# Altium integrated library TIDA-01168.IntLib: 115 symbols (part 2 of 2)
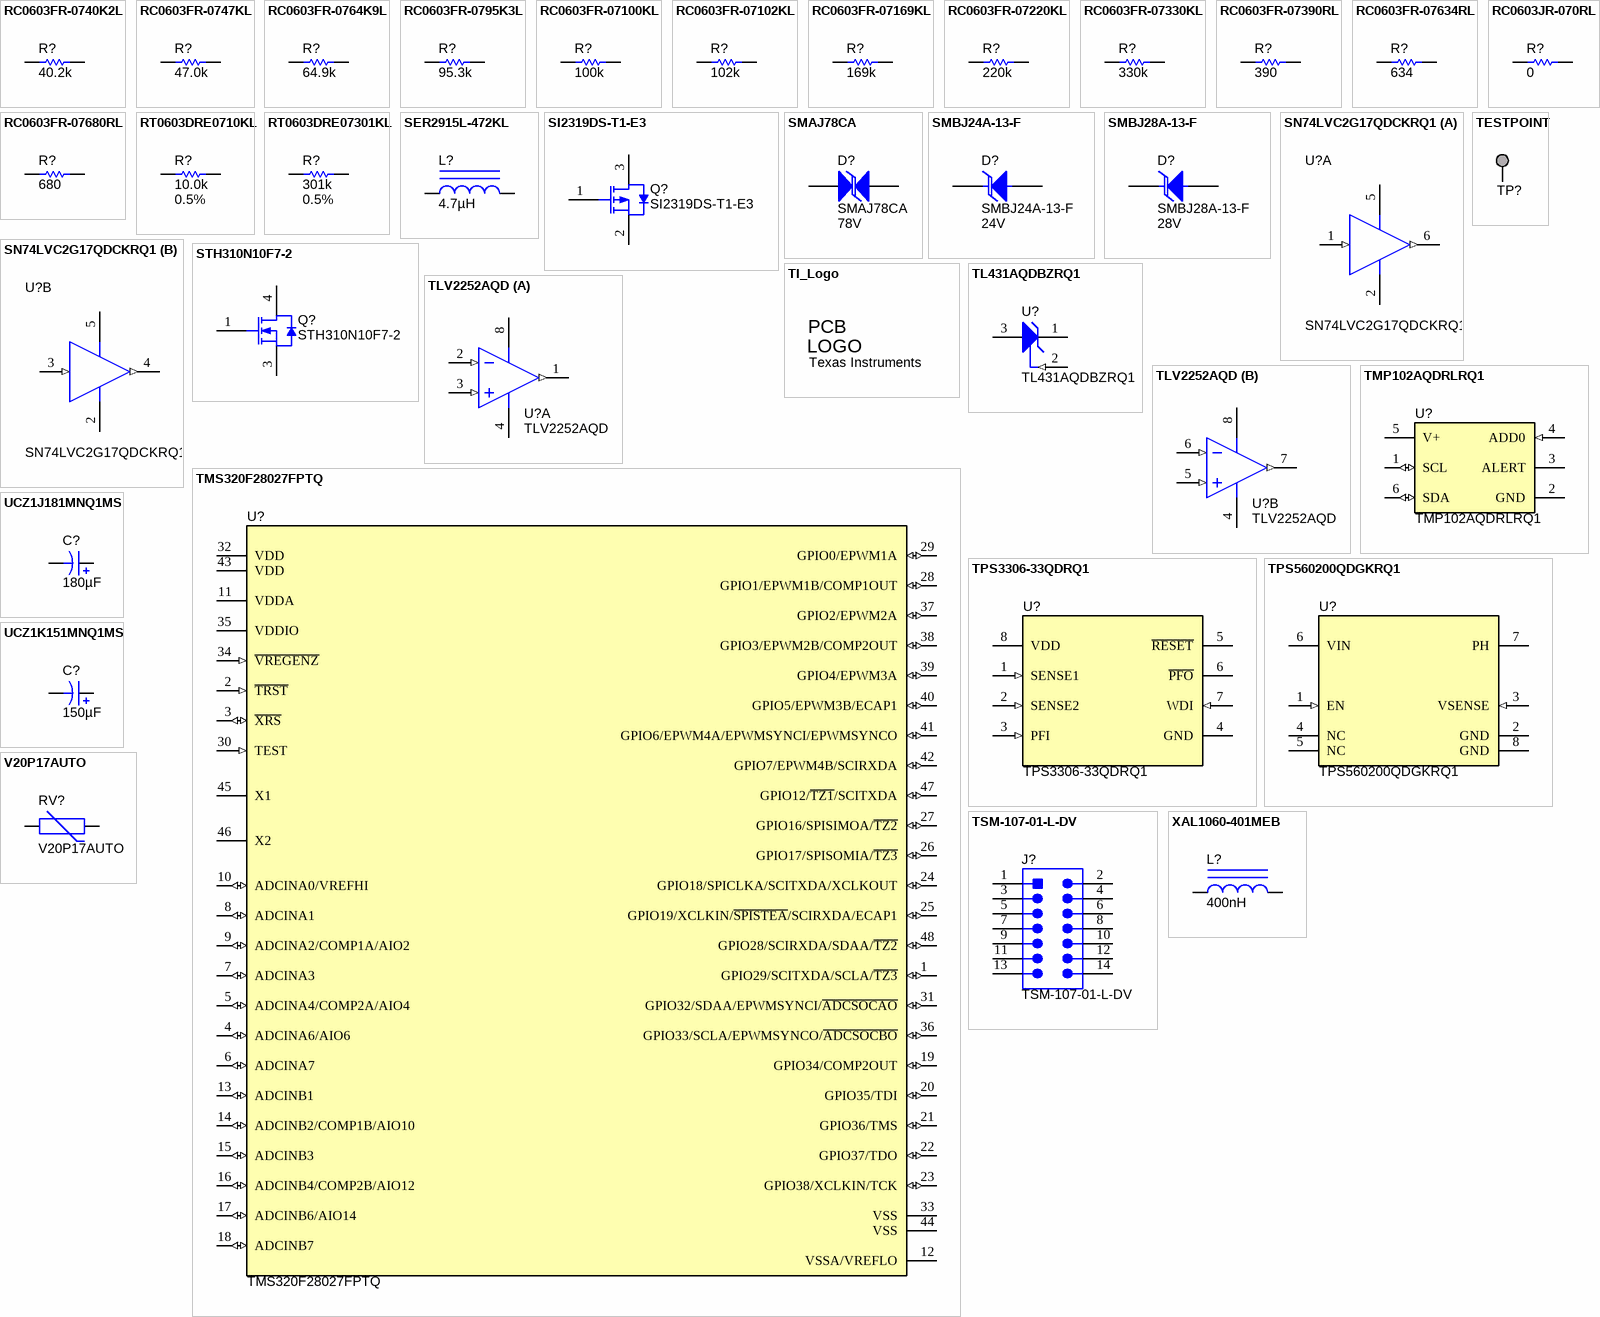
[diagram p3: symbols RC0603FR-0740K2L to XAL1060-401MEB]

## TESTPOINT
designator TP?  (value not drawn)  (no BOM)
TEST POINT.  No entry in BOM.
footprint TESTPOINT
footprint TP_VIA_018RND008
footprint TP_VIA_060RND040
footprint TP_25MIL-SMT
footprint TP_50MIL-25MILHOLE
footprint TP_60MIL-SMT
pins: 1

## TI_Logo
designator Logo?, comment Texas Instruments  (no BOM)
Texas Instrument Corporate Signature; SymbolCreator: codlsc
footprint TI_Stacked_SolderMask_Medium
footprint TI_Stacked_SolderMask_Small
footprint TI_Stacked_Overlay_Medium
footprint TI_Stacked_Overlay_Small
footprint TI_Horizontal_SolderMask_Medium
footprint TI_Horizontal_SolderMask_Small
footprint TI_Horizontal_Overlay_Medium
footprint TI_Horizontal_Overlay_Small
footprint TI_Symbol_SolderMask_Small
footprint TI_Symbol_Overlay_Medium
footprint TI_Symbol_Overlay_Small
footprint TI_Symbol_SolderMask_Medium

## TL431AQDBZRQ1
designator U?
Automotive Catalog Adjustable Precision Shunt Regulator, 34 ppm / degC, 100 mA, -40 to 125 degC, 3-pin SOT-23 (DBZ), Green (RoHS & no Sb/Br); Manufacturer: Texas Instruments; Alternate PartNumber: Equivalent; Initial Accuracy @ 25/deg C(%): 1; Iout/Iz(Max)(mA): 100; Min Iz for Regulation(uA): 600; SubFamily: Shunt Voltage Reference; Temp Coeff(Typ)(ppm/ degree C): 34; VO Adj(Max)(V): 36; VO Adj(Min)(V): 2.495
footprint DBZ0003A_N (SOT23, 3-Leads, Body 2.92x1.3 mm, Pitch 0.95 mm, IPC Medium Density)
footprint DBZ0003A_L (SOT23, 3-Leads, Body 2.92x1.3 mm, Pitch 0.95 mm, IPC High Density)
footprint DBZ0003A_M (SOT23, 3-Leads, Body 2.92x1.3 mm, Pitch 0.95 mm, IPC Low Density)
pins: 1 CATHODE, 2 REF (in), 3 ANODE (power)

## TLV2252AQD
designator U?
Low-Voltage Rail-to-Rail Dual Operational Amplifier, 2.7 to 8 V, -40 to 125 degC, 8-pin SOIC (D0008A), Green (RoHS & no Sb/Br); Manufacturer: Texas Instruments; Alternate PartNumber: Equivalent; CMRR(Min)(dB): 65; IIB(Max)(pA): 60; Iq per channel(Max)(mA): 0.0625; Number of Channels: 2; Offset Drift(Typ)(uV/C): 0.5; Slew Rate(Typ)(V/us): 0.1; Sub Family: Low Power Amp (<=500uA), Low Supply Voltage Amplifier (<=2.7V), Precision Amplifier; Total Supply Voltage(Max)(+5V is 5, +/-5V is 10): 8; Total Supply Voltage(Min)(+5V is 5, +/-5V is 10): 2.7; Vio (25C)(Max)(mV): 0.85; Vn at 1kHz(Typ)(nV/rtHz): 19
footprint D0008A_N (SOIC, 8-Leads, Body 4.9x3.9mm, Pitch 1.27mm, IPC Medium Density)
footprint D0008A_L (SOIC, 8-Leads, Body 4.9x3.9mm, Pitch 1.27mm, IPC High Density)
footprint D0008A_M (SOIC, 8-Leads, Body 4.9x3.9mm, Pitch 1.27mm, IPC Low Density)
pins on every part: 4 VDD-/GND (power), 8 VDD+ (power)
part A pins: 1 OUT1 (out), 2 IN1- (in), 3 IN1+ (in)
part B pins: 5 IN2+ (in), 6 IN2- (in), 7 OUT2 (out)

## TMP102AQDRLRQ1
designator U?
Low-Power Digital Temperature Sensor With SMBus and Two-Wire Serial Interface in SOT563, DRL0006A; Manufacturer: Texas Instruments; SymbolCreator: a0799628; SizeArea_mm2: 2.56; SizeAreaWB_mm2: 6.76; SizeX_mm: 1.6; SizeZ_mm: 0.6; CompType: IC; U/M: EA
footprint DRL0006A
pins: 1 SCL (io), 2 GND (power), 3 ALERT (oc), 4 ADD0 (in), 5 V+ (power), 6 SDA (io)
2 alternate drawings of the same symbol

## TMS320F28027FPTQ
designator U?
Piccolo Microcontroller, PT0048A; Alternate PartNumber: TMS320F28027FPTT; Manufacturer: Texas Instruments; SymbolCreator: Altium; SizeArea_mm2: 81; SizeAreaWB_mm2: 121; SizeX_mm: 9; SizeZ_mm: 1.6; CompType: IC; U/M: EA
footprint PT0048A_N
footprint PT0048A_M
footprint PT0048A_L
pins: 1 GPIO29/SCITXDA/SCLA/~{TZ3} (io), 2 ~{TRST} (in), 3 ~{XRS} (io), 4 ADCINA6/AIO6 (io), 5 ADCINA4/COMP2A/AIO4 (io), 6 ADCINA7 (io), 7 ADCINA3 (io), 8 ADCINA1 (io), 9 ADCINA2/COMP1A/AIO2 (io), 10 ADCINA0/VREFHI (io), 11 VDDA (power), 12 VSSA/VREFLO (power), 13 ADCINB1 (io), 14 ADCINB2/COMP1B/AIO10 (io), 15 ADCINB3 (io), 16 ADCINB4/COMP2B/AIO12 (io), 17 ADCINB6/AIO14 (io), 18 ADCINB7 (io), 19 GPIO34/COMP2OUT (io), 20 GPIO35/TDI (io), 21 GPIO36/TMS (io), 22 GPIO37/TDO (io), 23 GPIO38/XCLKIN/TCK (io), 24 GPIO18/SPICLKA/SCITXDA/XCLKOUT (io), 25 GPIO19/XCLKIN/~{SPISTEA}/SCIRXDA/ECAP1 (io), 26 GPIO17/SPISOMIA/~{TZ3} (io), 27 GPIO16/SPISIMOA/~{TZ2} (io), 28 GPIO1/EPWM1B/COMP1OUT (io), 29 GPIO0/EPWM1A (io), 30 TEST (in), 31 GPIO32/SDAA/EPWMSYNCI/~{ADCSOCAO} (io), 32 VDD (power), 33 VSS (power), 34 ~{VREGENZ} (in), 35 VDDIO (power), 36 GPIO33/SCLA/EPWMSYNCO/~{ADCSOCBO} (io), 37 GPIO2/EPWM2A (io), 38 GPIO3/EPWM2B/COMP2OUT (io), 39 GPIO4/EPWM3A (io), 40 GPIO5/EPWM3B/ECAP1 (io), 41 GPIO6/EPWM4A/EPWMSYNCI/EPWMSYNCO (io), 42 GPIO7/EPWM4B/SCIRXDA (io), 43 VDD (power), 44 VSS (power), 45 X1, 46 X2, 47 GPIO12/~{TZ1}/SCITXDA (io), 48 GPIO28/SCIRXDA/SDAA/~{TZ2} (io)

## TPS3306-33QDRQ1
designator U?
Dual Processor Supervisory Circuits with power Fail, D0008A; Manufacturer: Texas Instruments; SymbolCreator: Altium; SizeArea_mm2: 30.38; SizeAreaWB_mm2: 56.58; SizeX_mm: 4.9; SizeY_mm: 6.2; SizeZ_mm: 1.75; CompType: IC; U/M: EA
footprint D0008A_N
footprint D0008A_M
footprint D0008A_L
pins: 1 SENSE1 (in), 2 SENSE2 (in), 3 PFI (in), 4 GND (power), 5 ~{RESET} (oc), 6 ~{PFO} (oc), 7 WDI (in), 8 VDD (power)

## TPS560200QDGKRQ1
designator U?
4.5V to 18V Input, 500mA Synchronous Step Down SWIFT Converter with Advanced Eco-mode, DGK0008A; Alternate PartNumber: TPS560200QDGKTQ1; Manufacturer: Texas Instruments; SymbolCreator: a0411947; SizeArea_mm2: 15.655; SizeAreaWB_mm2: 35.955; SizeX_mm: 5.05; SizeY_mm: 3.1; SizeZ_mm: 1.1; CompType: IC; U/M: EA
footprint DGK0008A_N
footprint DGK0008A_M
footprint DGK0008A_L
pins: 1 EN (in), 2 GND (power), 3 VSENSE (in), 4 NC, 5 NC, 6 VIN (power), 7 PH (power), 8 GND (power)

## TSM-107-01-L-DV
designator J?
Header, 2.54mm, 7x2, Gold, SMT; Manufacturer: Samtec; SymbolCreator: a0412235; Pitch_mm: 2.54; Gender: Male; Shrouded: N; Row_Count: 2; Current_A: 5.4; Cert_CSA: Y
footprint Samtec_TSM-107-01-x-DV
pins: 1, 2, 3, 4, 5, 6, 7, 8, 9, 10, 11, 12, 13, 14

## UCZ1J181MNQ1MS
designator C?  ValueDisplayed: 180µF  (hidden comment: UCZ1J181MNQ1MS)
CAP, AL, 180 µF, 63 V, +/- 20%, 0.2 ohm, AEC-Q200 Grade 1, SMD; Manufacturer: Nichicon; Polarized: Y; CompType: Capacitor; Value: 180uF; U/M: EA; Cap_F: 0.00018; Tolerance_%: 20; Value1: 0.2 ohm; VDC_V: 63; Value2: 63V; ESR_ohm: 0.2; IRMS_A: 1; TaMin_C: -40; TaMax_C: 125; Cap_Case: 12.5x13.5mm; AEC Category: Q200
signal-integrity model Cap
simulation model Cap
footprint UCZ_1250x1350
pins: 1 +, 2 -

## UCZ1K151MNQ1MS
designator C?  ValueDisplayed: 150µF  (hidden comment: UCZ1K151MNQ1MS)
CAP, AL, 150 µF, 80 V, +/- 20%, 0.2 ohm, AEC-Q200 Grade 1, SMD; Manufacturer: Nichicon; Polarized: Y; CompType: Capacitor; Value: 150uF; U/M: EA; Cap_F: 0.00015; Tolerance_%: 20; Value1: 0.2 ohm; VDC_V: 80; Value2: 80V; ESR_ohm: 0.2; IRMS_A: 0.7; TaMin_C: -40; TaMax_C: 125; Cap_Case: 12.5x13.5mm; AEC Category: Q200; AEC Grade: 1
signal-integrity model Cap
simulation model Cap
footprint UCZ_1250x1350
pins: 1 +, 2 -

## V20P17AUTO
designator RV?
VARISTOR 27V, TH; Manufacturer: Littelfuse; SymbolCreator: a0412235
footprint Littelfuse_V20P17AUTO
pins: 1, 2

## XAL1060-401MEB
designator L?  ValueDisplayed: 400nH  (hidden comment: XAL1060-401MEB)
Inductor, Shielded, Composite, 400 nH, 36.8 A, 0.0008 ohm, AEC-Q200 Grade 1, SMD; Manufacturer: Coilcraft; Value: 400nH; Ind_H: 400.0E-9; Imax_A: 36.8; Irms: 36.8A @ 40C rise; Isat: 82A @ 30% inductance drop; DCR_ohm: 0.0008; Value2: 36.8A; AEC Category: Q200; AEC Qualified: Y; AEC Grade: 1
signal-integrity model Inductor
simulation model Inductor
footprint XAL1060
pins: 1, 2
